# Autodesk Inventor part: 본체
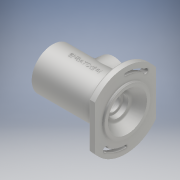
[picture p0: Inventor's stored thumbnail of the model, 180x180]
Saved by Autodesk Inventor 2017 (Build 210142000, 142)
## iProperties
Part Number: 본체
Material: 알루미늄 6061
Document SubType Name: Modeling
Designer: MRC
Density: 2.7 g/cm^3
Appearance: 알루미늄 - 평지
Author: MRC
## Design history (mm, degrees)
sketch "스케치1"
  geometry: L1 (47, 33.985)-(47, -33.985); L2 (-47, -33.985)-(-47, 33.985); A1 r 58 centre (0, 0) between (47, 33.985) and (-47, 33.985); A2 r 58 centre (0, 0) between (-47, -33.985) and (47, -33.985); 1 further point
  constraints: 4 end point, 4 point on circle, 2 centre point, 1 coincident, 1 parallel, 1 vertical
  dimensions: "d3" = 58 radius of A2; "d4" = 58 radius of A1; "d5" = 94 distance between parallel lines of L1 L2; "d6" = 47 distance from line of point (0, 0) L1
extrude "돌출1" new body sketch "스케치1" distance "d7" = 10; taper "d8" = 0 deg
sketch "스케치2"
  geometry: L1 (33.985, -47)-(-33.985, -47) reference; L2 (-33.985, 47)-(33.985, 47) reference; C1 r 36 at (0, 0); A1 r 58 centre (0, 0) between (33.985, -47) and (33.985, 47) reference; A2 r 58 centre (0, 0) between (-33.985, 47) and (-33.985, -47) reference; 1 further point
  constraints: 1 centre point, 1 coincident
  dimensions: "d9" = 72 diameter of C1
extrude "돌출2" join sketch "스케치2" distance "d10" = 3; taper "d11" = 0 deg
chamfer "모따기1" distance "d26" = 1; stored, may be unused: second distance "d27" = 2, angle "d28" = 45 deg
sketch "스케치4"
  geometry: L1 (-33.985, -47)-(33.985, -47) reference; L2 (33.985, 47)-(-33.985, 47) reference; C1 r 32 at (0, 0); A1 r 58 centre (0, 0) between (33.985, -47) and (33.985, 47) reference; A2 r 58 centre (0, 0) between (-33.985, 47) and (-33.985, -47) reference; 1 further point
  constraints: 1 centre point, 1 coincident
  dimensions: "d29" = 64 diameter of C1
extrude "돌출4" join sketch "스케치4" distance "d30" = 102; taper "d31" = 0 deg
fillet "모깎기1" dims "d32" = 3
node "작업 평면1"
node "작업 평면2"
sketch "스케치10"
  geometry: L1 (3, 35)-(3, -35) reference; L2 (3, 0)-(-112, 0); L3 (3, 30)-(-9.744, 20.897); L4 (-11, 18.456)-(-11, 15.404); L5 (-11.7, 15)-(-17.8, 15); L6 (-18.3, 14.5)-(-18.3, 11); L7 (-18.3, 11)-(-21, 11); L8 (-21, 11)-(-21, 12); L9 (-37, 18.5)-(-37, 24); L10 (-47.665, 26.047)-(-47.665, 25.836); L11 (-40, 27)-(-72, 27); L12 (-75, 24)-(-75, 18.5); L13 (-76, 17.5)-(-86, 17.5); L14 (-86, 17.5)-(-86, 18.5); L15 (-86, 18.5)-(-87.75, 18.5); L16 (-87.75, 18.5)-(-87.75, 17.5); L17 (-87.75, 17.5)-(-89, 17.5); L18 (-90, 18.5)-(-90, 19.5); L19 (-93, 22.5)-(-101, 22.5); L20 (-101, 22.5)-(-101, 24); L21 (-101, 24)-(-104, 24); L22 (-104, 24)-(-104, 22.5); L23 (-104, 22.5)-(-112, 22.5); L24 (-112, 32)-(-112, -32) reference; L25 (-11.7, 15)-(-11, 15.404); L26 (-76, 17.5)-(-75, 18.5); L27 (-89, 17.5)-(-90, 18.5); L28 (-112, 22.5)-(-112, 0); L29 (3, 30)-(3, 0); L30 (2, -36)-(2, 36) reference; L31 (-24, 15)-(-26, 15); L32 (-26, 15)-(-26, 16.9); L33 (-26.6, 17.5)-(-36, 17.5); L34 (-37, 18.5)-(-36, 17.5); A1 r 3 centre (-8, 18.456) between (-9.744, 20.897) and (-11, 18.456); A2 r 0.5 centre (-17.8, 14.5) between (-17.8, 15) and (-18.3, 14.5); A3 r 3 centre (-24, 12) between (-21, 12) and (-24, 15); A4 r 3 centre (-40, 24) between (-37, 24) and (-40, 27); A5 r 3 centre (-72, 24) between (-72, 27) and (-75, 24); A6 r 3 centre (-93, 19.5) between (-90, 19.5) and (-93, 22.5); A7 r 0.6 centre (-26.6, 16.9) between (-26, 16.9) and (-26.6, 17.5); 12 further points
  constraints: 62 end point, 24 point on line, 15 perpendicular, 14 point on circle, 13 tangent, 7 centre point, 4 horizontal, 2 vertical, 1 equal radius, 1 midpoint, 1 parallel
  dimensions: "d45" = 60 diameter of L3.start L2; "d46" = 40 diameter of point (-11, 20) L2; "d47" = 14 horizontal distance of point (-11, 20) L3.start; "d48" = 115 distance of L2.start L2.end; "d49" = 30 diameter of L5 L2; "d50" = 22 diameter of L7 L2; "d51" = 7.3 distance of point (-11, 15) point (-18.3, 15); "d55" = 54 diameter of L11 L2; "d57" = 35 diameter of L13 L2; "d58" = 11 distance of point (-75, 17.5) L13.end; "d59" = 1.75 distance of L14.end L15.end; "d60" = 37 diameter of L15 L2; "d61" = 4 distance between parallel lines of L18 L14; "d62" = 45 diameter of L19 L2; "d63" = 48 diameter of L21 L2; "d64" = 3 distance between parallel lines of L20 L22; "d65" = 8 distance from line of L22 L23.end; "d66" = 45 diameter of L23 L2; "d67" = 3 radius of A1; "d68" = 0.5 radius of A2; "d69" = 0.7 distance of L5.start point (-11, 15); "d70" = 30 deg angle of L5 L25; "d71" = 3 radius of A3; "d74" = 3 radius of A4 (derived); "d75" = 1 distance of L13.start point (-75, 17.5); "d76" = 1 distance of L12.end point (-75, 17.5) (= d75); "d77" = 1 distance of L17.end point (-90, 17.5) (= d75); "d78" = 1 distance of L18.start point (-90, 17.5) (= d77); "d79" = 3 radius of A6 (derived); "d148" = 5 distance between parallel lines of L8 L32; "d149" = 11 distance between parallel lines of L32 L9; "d150" = 29 distance between parallel lines of L1 L32; "d151" = 30 diameter of L31 L2; "d152" = 35 diameter of L33 L2; "d153" = 38 distance between parallel lines of L9 L12; "d155" = 0.6 radius of A7; "d156" = 1 distance of L9.start point (-37, 17.5); "d157" = 1 distance of L33.end point (-37, 17.5) (= d156)
revolve "회전1" sketch "스케치10" stored, may be unused: angle "d80" = 90 deg
feature "스레드1" dims "d81" = 10, "d82" = 0
node "작업 평면3"
sketch "스케치12"
  geometry: L1 (-3, -35)-(-3, 35) reference; L2 (112, -32)-(112, 32) reference; C1 r 25 at (56, 0); 1 further point
  constraints: 1 centre point
  dimensions: "d99" = 50 diameter of C1; "d154" = 56 distance from line of L2 C1.centre
extrude "돌출8" join sketch "스케치12" stored distance "d101" = 102; taper "d102" = 5 deg
hole "구멍2" diameter "d105" = 32; stored, may be unused: countersink angle "d109" = 90 deg, drill point angle "d111" = 118 deg; dims "d103" = 10, "d104" = 10, "d106" = 6, "d107" = 4, "d108" = 2, "d110" = 20
fillet "모깎기3" dims "d112" = 3
chamfer "모따기2" distance "d113" = 1; stored, may be unused: second distance "d114" = 2, angle "d115" = 45 deg
sketch "스케치13"
  geometry: C1 r 25 at (0, 0) reference; C2 r 17 at (0, 0) reference; A1 r 20.5 centre (0, 0) between (0, -20.5) and (0, 20.5); 1 further point
  constraints: 2 point on circle, 1 centre point, 1 coincident
  dimensions: "d116" = 41 diameter of A1
hole "구멍3" sketch "스케치13" at (0, -20.5), (0, 20.5) diameter "d117" = 2.621; stored, may be unused: countersink angle "d121" = 90 deg, drill point angle "d123" = 118 deg; dims "d118" = 6, "d119" = 4, "d120" = 2, "d122" = 8
sketch "스케치14"
  geometry: L1 (0, 0)-(-36.77, 30.854); L2 (0, 0)-(48, 0); L3 (0, 0)-(36.77, -30.854); L4 (0, 0)-(48, 0); L5 (0, 0)-(0, 37.337); L6 (0, 0)-(36.77, 30.854); A1 r 2.25 centre (36.77, 30.854) between (38.494, 32.3) and (35.047, 29.408); A2 r 45.75 centre (0, 0) between (45.75, 0) and (35.047, 29.408); A3 r 50.25 centre (0, 0) between (50.25, 0) and (38.494, 32.3); A4 r 2.25 centre (48, 0) between (45.75, 0) and (50.25, 0); A5 r 45.75 centre (0, 0) between (-45.75, 0) and (-35.047, -29.408); A6 r 50.25 centre (0, 0) between (-50.25, 0) and (-38.494, -32.3); A7 r 2.25 centre (-48, 0) between (-45.75, 0) and (-50.25, 0); A8 r 2.25 centre (-36.77, -30.854) between (-38.494, -32.3) and (-35.047, -29.408); 1 further point
  constraints: 16 point on circle, 12 end point, 8 centre point, 2 coincident, 2 equal length, 2 horizontal, 1 point on line, 1 symmetric about line, 1 vertical
  dimensions: "d125" = 140 deg angle of L2 L1; "d130" = 40 deg angle of L3 L4
extrude "돌출9" cut sketch "스케치14" distance "d131" = 102; taper "d132" = 0 deg
sketch "스케치16"
  geometry: L1 (-33, -44)-(33, -44) reference; L2 (33, 44)-(-33, 44) reference; C1 r 20.692 at (0, 0) reference; C2 r 35 at (0, 0) reference; C3 r 4 at (36.77, 30.854); C4 r 4 at (-36.77, -30.854); A1 r 2.25 centre (-48, 0) between (-45.75, 0) and (-50.25, 0) reference; A2 r 50.25 centre (0, 0) between (-50.25, 0) and (-38.494, -32.3) reference; A3 r 2.25 centre (-36.77, -30.854) between (-38.494, -32.3) and (-35.047, -29.408) reference; A4 r 45.75 centre (0, 0) between (-45.75, 0) and (-35.047, -29.408) reference; A5 r 45.75 centre (0, 0) between (45.75, 0) and (35.047, 29.408) reference; A6 r 2.25 centre (48, 0) between (45.75, 0) and (50.25, 0) reference; A7 r 50.25 centre (0, 0) between (50.25, 0) and (38.494, 32.3) reference; A8 r 2.25 centre (36.77, 30.854) between (38.494, 32.3) and (35.047, 29.408) reference; A9 r 55 centre (0, 0) between (33, -44) and (33, 44) reference; A10 r 55 centre (0, 0) between (-33, 44) and (-33, -44) reference; 1 further point
  constraints: 2 centre point, 2 coincident
  dimensions: "d141" = 8 diameter of C3; "d142" = 8 diameter of C4
extrude "돌출11" cut sketch "스케치16" stored distance "d143" = 4.4; taper "d144" = 0 deg
node "작업 평면4"
sketch "스케치17"
  geometry: L1 (10, 47)-(10, -47) reference; 3 further points
  constraints: 1 horizontal alignment, 1 midpoint, 1 other
  dimensions: "d145" = 62 distance from line of L1 point (-52, 0)
feature "엠보싱1" sketch "스케치17" dims "d3" = 58, "d4" = 58, "d5" = 94, "d6" = 47, "d146" = 0.5, "d147" = 0
sketch "스케치18"
  geometry: L1 (-33, -44)-(33, -44) reference; L2 (33, 44)-(-33, 44) reference; C1 r 20.692 at (0, 0) reference; C2 r 35 at (0, 0) reference; A1 r 4 centre (-36.77, -30.854) between (-40.58, -29.636) and (-37.033, -26.862) reference; A2 r 45.75 centre (0, 0) between (-45.75, 0) and (-37.033, -26.862) reference; A3 r 2.25 centre (-48, 0) between (-45.75, 0) and (-50.25, 0) reference; A4 r 50.25 centre (0, 0) between (-50.25, 0) and (-40.58, -29.636) reference; A5 r 4 centre (36.77, 30.854) between (40.58, 29.636) and (37.033, 26.862) reference; A6 r 45.75 centre (0, 0) between (45.75, 0) and (37.033, 26.862) reference; A7 r 2.25 centre (48, 0) between (45.75, 0) and (50.25, 0) reference; A8 r 50.25 centre (0, 0) between (50.25, 0) and (40.58, 29.636) reference; A9 r 55 centre (0, 0) between (33, -44) and (33, 44) reference; A10 r 55 centre (0, 0) between (-33, 44) and (-33, -44) reference; A11 r 4 centre (36.77, 30.854) between (39.834, 33.425) and (33.706, 28.283); A12 r 4 centre (48, 0) between (44, 0) and (52, 0); A13 r 4 centre (-48, 0) between (-44, 0) and (-52, 0); A14 r 4 centre (-36.77, -30.854) between (-39.834, -33.425) and (-33.706, -28.283); A15 r 52 centre (0, 0) between (-52, 0) and (-39.834, -33.425); A16 r 44 centre (0, 0) between (-44, 0) and (-33.706, -28.283); A17 r 52 centre (0, 0) between (52, 0) and (39.834, 33.425); A18 r 44 centre (0, 0) between (44, 0) and (33.706, 28.283); 1 further point
  constraints: 20 point on circle, 8 centre point, 6 coincident, 1 concentric
  dimensions: "d158" = 8 diameter of A12; "d159" = 8 diameter of A13
extrude "돌출12" cut sketch "스케치18" distance "d165" = 4.4; taper "d166" = 0 deg
node "솔리드1"
node "투영된 루프1"
node "투영된 루프2"
node "투영된 루프5"
node "절단 모서리 투영4"
node "절단 모서리 투영5"
other parameters: "d0" = 58, "d12" = 96, "d17" = 4, "d18" = 4, "d34" = -14, "d38" = 38, "d98" = 38, "d124" = 96, "d128" = 2.25, "d129" = 2.25, "d137" = 4, "d138" = 4, "d163" = 4, "d164" = 4
